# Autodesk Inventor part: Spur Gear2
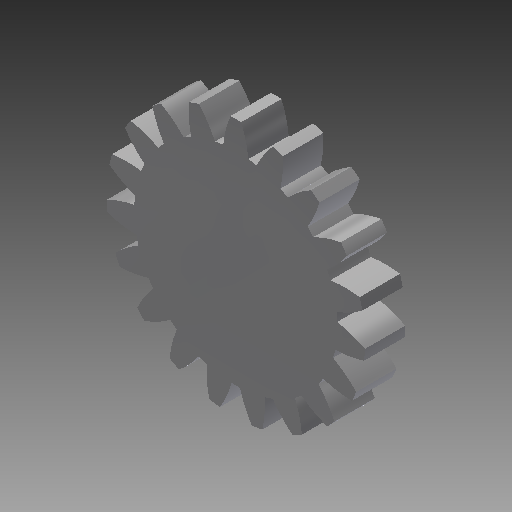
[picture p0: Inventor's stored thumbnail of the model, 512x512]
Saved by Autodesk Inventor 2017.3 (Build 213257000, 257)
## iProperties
Created: 2020-03
Part Number: Spur Gear2
Material: Steel
Document SubType Name: Modeling
Designer: Tim_G
Categories: <?xml version="1.0" encoding="UTF-16"?> <MemberInstance><Categories><FamilyTemplate><FamilyTemplateParameter ValueType="xs:double" Id="1" ObjectReferenceKey="da
Density: 1 g/cm^3
Appearance: Steel
CustomPartVersion: 1
Author: Tim_G
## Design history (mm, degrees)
sketch "Sketch1"
  geometry: C1 r 15.991 at (0, 0)
  constraints: 1 centre point
  dimensions: "d0" = 31.98165 diameter of C1 (= da_da)
extrude "Extrusion1" new body sketch "Sketch1" distance "d1" = 5 (= da_b); taper "d2" = 0 deg
workplane "Work Plane2"
sketch "Sketch2"
  geometry: C1 r 15.991 at (0, 0) reference; C2 r 14.468 at (0, 0)
  constraints: 1 centre point, 1 coincident
  dimensions: "d3" = 28.93578 diameter of C2 (= da_dw)
feature "Pitch Diameter" sketch "Sketch2" dims "d4" = 10, "d5" = 0
workplane "Work Plane8"
workplane "Work Plane9"
feature "Spur Gear" dims "d5" = 0, "da_b" = 5, "da_d" = 28.93578, "da_aw" = 25.12844, "da_da" = 31.98165, "da_df" = 25.12844, "da_dw" = 28.93578, angle "da_beta" = 0 deg, "da_lefttooth" = 0, "da_righttooth" = 0
body "Solid1"
body "Srf1"
other parameters: "d16" = 25.12844 (= da_aw), "d17" = 0, "d34" = 1.65347 (computed from da_z), "d39" = 0, "d41" = 0, "d43" = 25.12844 (= da_aw), "d46" = 25.12844 (= da_aw), "d47" = 0, "d48" = 0
